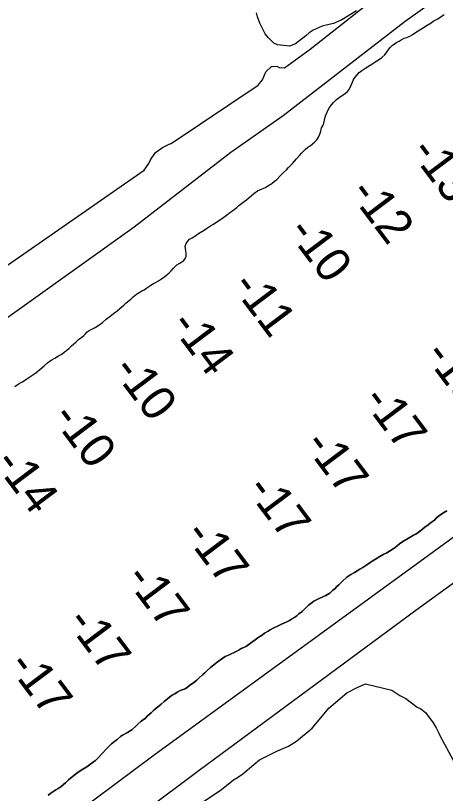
# Model space of a CAD drawing. Extents: x 3683613 to 3738215, y 469626 to 495384.
# Drawn here: x 3693984 to 3694543, y 491252 to 492263 of the extents above; entities that cross this region are included whole.
import ezdxf

# ---------------------------------------------------------------- set-up
doc = ezdxf.new("R2010")
doc.units = 0
for name, color, linetype in [('V-LEVE-TOET', 7, 'Continuous'), ('V-RIVR-JETY', 7, 'Continuous'), ('V-SITE-VEGE', 7, 'Continuous'), ('V-TOPO-SHOR', 7, 'Continuous'), ('V-TOPO-SPOT', 7, 'Continuous')]:
    doc.layers.add(name, color=color, linetype=linetype)

msp = doc.modelspace()

# ---------------------------------------------------------------- linework, layer by layer
at = {"layer": 'V-LEVE-TOET'}
for points in [[(3695280.6, 492831.8), (3695045.1, 492660.8), (3694810.9, 492483.2), (3694490.9, 492255), (3694332.2, 492132.7), (3694264.1, 492084.7), (3694138.5, 491987.9), (3693926.7, 491837), (3693737.7, 491697.5), (3693640.3, 491627.5), (3693587.1, 491587.3), (3693561.1, 491567.6), (3693375.6, 491432.8), (3693131.5, 491252.5)], [(3693943.4, 491917.9), (3694151.5, 492062.1), (3694157.4, 492070.6), (3694159.6, 492075.3), (3694166.3, 492084.7), (3694175.5, 492091.5), (3694184.1, 492095.6), (3694186.6, 492096.6), (3694299.6, 492172.4), (3694305.2, 492179.1), (3694309.5, 492189.6), (3694316.8, 492196.4), (3694323.9, 492197.1), (3694326.9, 492195.1), (3694333.8, 492194.9), (3694367.2, 492219.1), (3694555.4, 492367.6)], [(3692742.2, 490254.9), (3693119.2, 490531), (3693505.2, 490808.5), (3693831.6, 491054.9), (3694164.5, 491302.4), (3694594.4, 491615), (3694776.6, 491744.1), (3694908.8, 491836.2), (3695045.7, 491937.3), (3695073, 491960.6), (3695095.4, 491971.2), (3695099.9, 491970), (3695106.2, 491964.6), (3695111.3, 491953.8), (3695114, 491939.2), (3695107.6, 491925.6), (3695067.8, 491896.4), (3694823.2, 491720.7), (3694504.8, 491489.9), (3694223, 491282.1), (3693783.2, 490953.5), (3693425, 490687.1), (3693111.9, 490453.6), (3692756, 490200.1)]]:
    msp.add_lwpolyline(points, dxfattribs=at)
at = {"layer": 'V-RIVR-JETY'}
for points in [[(3694404.5, 491523.4), (3694406.8, 491525.6), (3694409, 491527.8), (3694414.7, 491533.1), (3694420.3, 491536.7), (3694424.7, 491539.5), (3694431.9, 491543.6), (3694435.9, 491546), (3694442.1, 491550.2), (3694445.3, 491552.2), (3694448, 491554), (3694452.1, 491556.8), (3694457.8, 491560.1), (3694462.9, 491563.1), (3694466.7, 491565.1), (3694470.5, 491567.2), (3694475.2, 491570), (3694477.9, 491572), (3694480.5, 491574), (3694483.5, 491576.4), (3694487.9, 491579.6), (3694493, 491582.6), (3694498.1, 491585.8), (3694501.5, 491587.8), (3694504.5, 491589.3), (3694507.6, 491591.5), (3694511.1, 491594.1), (3694516.4, 491598.2), (3694520.8, 491601.1), (3694525.1, 491604.6), (3694528.9, 491607.4), (3694531.5, 491610.2), (3694533.9, 491612.4), (3694539.6, 491616.6), (3694544.7, 491619.6)], [(3694026.9, 491250), (3694030.3, 491252.6), (3694032.9, 491254.4), (3694036.7, 491257.2), (3694039.9, 491259), (3694043.7, 491261.4), (3694049.2, 491266.2), (3694053.3, 491270), (3694060.1, 491275.7), (3694064.2, 491278.9), (3694068.4, 491281.7), (3694071.8, 491283.9), (3694077.1, 491287), (3694080.5, 491289.4), (3694085.6, 491293.4), (3694088.2, 491295.2), (3694092.5, 491299.5), (3694096.1, 491303.5), (3694103.4, 491311), (3694106, 491313.7), (3694109, 491316.7), (3694113.3, 491320.1), (3694115.8, 491322.1), (3694120.6, 491326.5), (3694123.3, 491328.1), (3694129.7, 491331.7), (3694135.4, 491335.1), (3694140.9, 491340.1), (3694143.1, 491342.3), (3694147.6, 491346.4), (3694153.3, 491350.3), (3694155.5, 491352.6), (3694160.6, 491357.2), (3694164.2, 491360.4), (3694166.8, 491362.6), (3694173.6, 491368.5), (3694177.5, 491371.7), (3694181.7, 491375.3), (3694184.3, 491377.3), (3694187.9, 491379.9), (3694191.3, 491381.9), (3694194.5, 491383.9), (3694198.5, 491385.9), (3694204.6, 491388.4), (3694207.8, 491390.6), (3694210.3, 491392.4), (3694216.1, 491396.4), (3694219.9, 491399.4), (3694222.3, 491401.6), (3694227.8, 491406.8), (3694230.2, 491409.1), (3694233.2, 491411.9), (3694237.7, 491415.9), (3694242.2, 491419.5), (3694246.6, 491422.9), (3694253.9, 491428.3), (3694257, 491430.1), (3694261.1, 491432.1), (3694272, 491437.4), (3694274.8, 491439), (3694277.7, 491440.5), (3694280.9, 491442.1), (3694284.5, 491443.9), (3694289.6, 491447.7), (3694295.6, 491451.9), (3694299.2, 491454.3), (3694301.7, 491456.3), (3694305.1, 491458.3), (3694308.1, 491460.5), (3694312.6, 491463.3), (3694315.1, 491464.8), (3694319.1, 491467), (3694324.8, 491469.8), (3694330.1, 491472.1), (3694336, 491474.8), (3694340.2, 491477), (3694343.2, 491478.8), (3694346, 491480.6), (3694349.8, 491483.2), (3694352.6, 491485.6), (3694356.8, 491488.6), (3694360.9, 491492.8), (3694365, 491496.9), (3694369.7, 491500.5), (3694372.2, 491502.1), (3694378.3, 491505), (3694384.7, 491508.2), (3694387.6, 491509.5), (3694392.7, 491512.7), (3694396.1, 491515.9), (3694399.3, 491518.3), (3694401.9, 491521), (3694404.5, 491523.4)]]:
    msp.add_lwpolyline(points, dxfattribs=at)
at = {"layer": 'V-SITE-VEGE'}
for points in [[(3694427.5, 492269), (3694408.3, 492257.1), (3694397.7, 492252.6), (3694386.4, 492249.7), (3694382.7, 492249.1), (3694371.3, 492243.8), (3694366, 492240.3), (3694361.5, 492236.4), (3694348.3, 492226), (3694340.6, 492223), (3694325, 492224.6), (3694320.2, 492226.8), (3694312.8, 492234.2), (3694308.9, 492239.2), (3694304, 492248.6), (3694301.7, 492252.7), (3694298.7, 492261.2), (3694297.7, 492266.4)], [(3694228.8, 491241.8), (3694250.1, 491256.1), (3694258.4, 491262.7), (3694267.8, 491270), (3694272.7, 491273.1), (3694279.7, 491277.7), (3694294.1, 491290.1), (3694301.5, 491295.9), (3694324, 491307.3), (3694339, 491313.7), (3694349.7, 491320.2), (3694369.9, 491337.3), (3694383.2, 491353), (3694391.5, 491363.2), (3694415, 491383), (3694428.5, 491390.2), (3694435.4, 491393.2), (3694439.1, 491394.7)], [(3694439.1, 491394.7), (3694473.4, 491386.5), (3694484, 491379.8), (3694491.5, 491375.5)], [(3694491.5, 491375.5), (3694506.5, 491364.6), (3694511.2, 491362.1), (3694517.1, 491357.5), (3694527.2, 491344.3), (3694531, 491337.4), (3694534.4, 491330.5), (3694536.3, 491326.8), (3694553.1, 491295.7)]]:
    msp.add_lwpolyline(points, dxfattribs=at)
at = {"layer": 'V-TOPO-SHOR'}
for points in [[(3694317.3, 492044.8), (3694320.9, 492047.6), (3694323.9, 492050), (3694329.2, 492055.5), (3694332.5, 492058.9), (3694336.3, 492062.5), (3694339.1, 492065.2), (3694341.7, 492068), (3694344.2, 492070.6), (3694346.8, 492073.7), (3694349.4, 492076.5), (3694353.7, 492081.6), (3694356.1, 492084.2), (3694360.8, 492088.7), (3694364.2, 492091.7), (3694367.2, 492093.7), (3694370.2, 492096.3), (3694373.2, 492098.7), (3694375.8, 492101.3), (3694378.1, 492104.8), (3694379.9, 492108.9), (3694381.3, 492112.4), (3694382.2, 492116.8), (3694383.8, 492119.6), (3694384.9, 492123.1), (3694385.7, 492126.7), (3694387.3, 492132.4), (3694389.3, 492137.2), (3694390.6, 492140.5), (3694392.4, 492143.5), (3694394.8, 492146.6), (3694397.6, 492150), (3694401.5, 492153.9), (3694404.9, 492156.5), (3694407.8, 492158.5), (3694411.4, 492160.7), (3694415.7, 492163.9), (3694418.1, 492166.5), (3694420.7, 492172.5), (3694422.1, 492176.2), (3694423.6, 492179.5), (3694425.8, 492182.7), (3694428.4, 492185.6), (3694431, 492188.6), (3694434.2, 492191.2), (3694436.8, 492193.2), (3694439.7, 492195), (3694447.3, 492199.6), (3694450.5, 492201.8), (3694453.7, 492204), (3694457.3, 492205.9), (3694460.5, 492208.3), (3694464.2, 492211.8), (3694466.5, 492214.8), (3694469.4, 492218.9), (3694471.1, 492221.3), (3694473.9, 492223.8), (3694476.9, 492226.2), (3694480, 492228), (3694482.8, 492229.5), (3694485.5, 492231.3), (3694489.6, 492233.3), (3694492.9, 492234.2), (3694496.9, 492235.8), (3694499.7, 492237.6), (3694504.3, 492240.6), (3694509.9, 492244.3), (3694514.5, 492247.1), (3694519.4, 492250.3), (3694524.5, 492253.5), (3694527.1, 492255.3), (3694533, 492258.7), (3694538.7, 492262.2), (3694541.5, 492264)], [(3694509.9, 492244.3), (3694514.5, 492247.1), (3694519.4, 492250.3), (3694524.5, 492253.5), (3694527.1, 492255.3), (3694533, 492258.7), (3694538.7, 492262.2), (3694541.5, 492264)], [(3694200.6, 491942.7), (3694202.9, 491944.7), (3694204.9, 491947.2), (3694206, 491950), (3694206.1, 491953.8), (3694205.8, 491957.3), (3694204.9, 491963.4), (3694206.1, 491966.5), (3694208.3, 491969.7), (3694210.6, 491972.2), (3694213.8, 491974.2), (3694217.2, 491976.1), (3694221, 491978.7), (3694224.2, 491981.1), (3694229.3, 491984.1), (3694232.7, 491986.1), (3694237.8, 491989.5), (3694241.6, 491991.7), (3694248.4, 491996.5), (3694252, 491998.6), (3694255.2, 492001), (3694258.6, 492003.6), (3694264.1, 492007.6), (3694266.7, 492009.4), (3694272, 492013.4), (3694274.4, 492015.9), (3694281.4, 492021.3), (3694284.6, 492023.5), (3694290.8, 492028.9), (3694294, 492031.7), (3694298.6, 492035.1), (3694305, 492037.7), (3694309.4, 492039.4), (3694312.4, 492041.4), (3694317.3, 492044.8), (3694320.9, 492047.6), (3694323.9, 492050), (3694329.2, 492055.5), (3694332.5, 492058.9), (3694336.3, 492062.5), (3694339.1, 492065.2), (3694341.7, 492068), (3694344.2, 492070.6), (3694346.8, 492073.7), (3694349.4, 492076.5), (3694353.7, 492081.6), (3694356.1, 492084.2), (3694360.8, 492088.7), (3694364.2, 492091.7), (3694367.2, 492093.7), (3694370.2, 492096.3), (3694373.2, 492098.7), (3694375.8, 492101.3), (3694378.1, 492104.8), (3694379.9, 492108.9), (3694381.3, 492112.4), (3694382.2, 492116.8), (3694383.8, 492119.6), (3694384.9, 492123.1), (3694385.7, 492126.7), (3694387.3, 492132.4), (3694389.3, 492137.2), (3694390.6, 492140.5), (3694392.4, 492143.5), (3694394.8, 492146.6), (3694397.6, 492150), (3694401.5, 492153.9), (3694404.9, 492156.5), (3694407.8, 492158.5), (3694411.4, 492160.7), (3694415.7, 492163.9), (3694418.1, 492166.5), (3694420.7, 492172.5), (3694422.1, 492176.2), (3694423.6, 492179.5), (3694425.8, 492182.7), (3694428.4, 492185.6), (3694431, 492188.6), (3694434.2, 492191.2), (3694436.8, 492193.2), (3694439.7, 492195), (3694447.3, 492199.6), (3694450.5, 492201.8), (3694453.7, 492204), (3694457.3, 492205.9), (3694460.5, 492208.3), (3694464.2, 492211.8), (3694466.5, 492214.8), (3694469.4, 492218.9), (3694471.1, 492221.3), (3694473.9, 492223.8), (3694476.9, 492226.2), (3694480, 492228), (3694482.8, 492229.5), (3694485.5, 492231.3), (3694489.6, 492233.3), (3694492.9, 492234.2), (3694496.9, 492235.8), (3694499.7, 492237.6), (3694504.3, 492240.6), (3694509.9, 492244.3)], [(3693983.5, 491780.9), (3693986.3, 491783.1), (3693989.2, 491784.7), (3693993.2, 491786.9), (3693997.7, 491789.9), (3694003, 491793.7), (3694009.2, 491797.9), (3694012.8, 491800.5), (3694015.8, 491802.9), (3694021.5, 491807.7), (3694025.8, 491811.7), (3694030.7, 491815.1), (3694035.4, 491817.9), (3694040.2, 491820.9), (3694044.3, 491823), (3694047.9, 491825.9), (3694050.4, 491827.9), (3694054.1, 491830.9), (3694057.1, 491833.7), (3694059.6, 491835.9), (3694062.8, 491838.5), (3694066.3, 491841.8), (3694070.5, 491845.2), (3694073.1, 491847), (3694075.4, 491849.4), (3694077.6, 491851.8), (3694080.1, 491853.8), (3694084.4, 491855.8), (3694087.7, 491857.6), (3694092.4, 491860.6), (3694097.5, 491864.2), (3694102, 491868.2), (3694106.7, 491872), (3694111.6, 491875.8), (3694116.5, 491879.2), (3694120.1, 491882.2), (3694125, 491886.7), (3694128.2, 491889.7), (3694134, 491894.5), (3694137.2, 491897.3), (3694141.5, 491900.7), (3694145.7, 491903.5), (3694148.5, 491905.1), (3694151.4, 491906.7), (3694155, 491908.9), (3694157.6, 491910.7), (3694160.1, 491912.5), (3694163.7, 491914.6), (3694166.9, 491916.4), (3694170.3, 491918.4), (3694174.1, 491921), (3694178.2, 491924), (3694181.1, 491925.8), (3694183.9, 491928.6), (3694186.5, 491931), (3694189.7, 491934.5), (3694193.8, 491938.9), (3694196.8, 491940.7), (3694200.6, 491942.7), (3694202.9, 491944.7), (3694204.9, 491947.2), (3694206, 491950), (3694206.1, 491953.8), (3694205.8, 491957.3), (3694204.9, 491963.4), (3694206.1, 491966.5), (3694208.3, 491969.7), (3694210.6, 491972.2), (3694213.8, 491974.2), (3694217.2, 491976.1), (3694221, 491978.7), (3694224.2, 491981.1), (3694229.3, 491984.1), (3694232.7, 491986.1), (3694237.8, 491989.5), (3694241.6, 491991.7), (3694248.4, 491996.5), (3694252, 491998.6), (3694255.2, 492001), (3694258.6, 492003.6), (3694264.1, 492007.6), (3694266.7, 492009.4), (3694272, 492013.4), (3694274.4, 492015.9), (3694281.4, 492021.3), (3694284.6, 492023.5), (3694290.8, 492028.9), (3694294, 492031.7), (3694298.6, 492035.1), (3694305, 492037.7), (3694309.4, 492039.4), (3694312.4, 492041.4), (3694317.3, 492044.8)], [(3693983.5, 491780.9), (3693986.3, 491783.1), (3693989.2, 491784.7), (3693993.2, 491786.9), (3693997.7, 491789.9), (3694003, 491793.7), (3694009.2, 491797.9), (3694012.8, 491800.5), (3694015.8, 491802.9), (3694021.5, 491807.7), (3694025.8, 491811.7), (3694030.7, 491815.1), (3694035.4, 491817.9), (3694040.2, 491820.9), (3694044.3, 491823), (3694047.9, 491825.9), (3694050.4, 491827.9), (3694054.1, 491830.9), (3694057.1, 491833.7), (3694059.6, 491835.9), (3694062.8, 491838.5), (3694066.3, 491841.8), (3694070.5, 491845.2), (3694073.1, 491847), (3694075.4, 491849.4), (3694077.6, 491851.8), (3694080.1, 491853.8), (3694084.4, 491855.8), (3694087.7, 491857.6), (3694092.4, 491860.6), (3694097.5, 491864.2), (3694102, 491868.2), (3694106.7, 491872), (3694111.6, 491875.8), (3694116.5, 491879.2), (3694120.1, 491882.2), (3694125, 491886.7), (3694128.2, 491889.7), (3694134, 491894.5), (3694137.2, 491897.3), (3694141.5, 491900.7), (3694145.7, 491903.5), (3694148.5, 491905.1), (3694151.4, 491906.7), (3694155, 491908.9), (3694157.6, 491910.7), (3694160.1, 491912.5), (3694163.7, 491914.6), (3694166.9, 491916.4), (3694170.3, 491918.4), (3694174.1, 491921), (3694178.2, 491924), (3694181.1, 491925.8), (3694183.9, 491928.6), (3694186.5, 491931), (3694189.7, 491934.5), (3694193.8, 491938.9), (3694196.8, 491940.7), (3694200.6, 491942.7)], [(3694544.7, 491619.6), (3694539.6, 491616.6), (3694533.9, 491612.4), (3694531.5, 491610.2), (3694528.9, 491607.4), (3694525.1, 491604.6), (3694520.8, 491601.1), (3694516.4, 491598.2), (3694511.1, 491594.1), (3694507.6, 491591.5), (3694504.5, 491589.3), (3694501.5, 491587.8), (3694498.1, 491585.8), (3694493, 491582.6), (3694487.9, 491579.6), (3694483.5, 491576.4), (3694480.5, 491574), (3694477.9, 491572), (3694475.2, 491570), (3694470.5, 491567.2), (3694466.7, 491565.1), (3694462.9, 491563.1), (3694457.8, 491560.1), (3694452.1, 491556.8), (3694448, 491554), (3694445.3, 491552.2), (3694442.1, 491550.2), (3694435.9, 491546), (3694431.9, 491543.6), (3694424.7, 491539.5), (3694420.3, 491536.7), (3694414.7, 491533.1), (3694409, 491527.8), (3694406.8, 491525.6), (3694404.5, 491523.4), (3694401.9, 491521), (3694399.3, 491518.3), (3694396.1, 491515.9), (3694392.7, 491512.7), (3694387.6, 491509.5), (3694384.7, 491508.2), (3694378.3, 491505), (3694372.2, 491502.1), (3694369.7, 491500.5), (3694365, 491496.9), (3694360.9, 491492.8), (3694356.8, 491488.6), (3694352.6, 491485.6), (3694349.8, 491483.2), (3694346, 491480.6), (3694343.2, 491478.8), (3694340.2, 491477), (3694336, 491474.8), (3694330.1, 491472.1), (3694324.8, 491469.8), (3694319.1, 491467), (3694315.1, 491464.8), (3694312.6, 491463.3), (3694308.1, 491460.5), (3694305.1, 491458.3), (3694301.7, 491456.3), (3694299.2, 491454.3), (3694295.6, 491451.9), (3694289.6, 491447.7), (3694284.5, 491443.9), (3694280.9, 491442.1), (3694277.7, 491440.5), (3694274.8, 491439), (3694272, 491437.4), (3694261.1, 491432.1), (3694257, 491430.1), (3694253.9, 491428.3), (3694246.6, 491422.9), (3694242.2, 491419.5), (3694237.7, 491415.9), (3694233.2, 491411.9), (3694230.2, 491409.1), (3694227.8, 491406.8), (3694222.3, 491401.6), (3694219.9, 491399.4), (3694216.1, 491396.4), (3694210.3, 491392.4), (3694207.8, 491390.6), (3694204.6, 491388.4), (3694198.5, 491385.9), (3694194.5, 491383.9), (3694191.3, 491381.9), (3694187.9, 491379.9), (3694184.3, 491377.3), (3694181.7, 491375.3), (3694177.5, 491371.7), (3694173.6, 491368.5), (3694166.8, 491362.6), (3694164.2, 491360.4), (3694160.6, 491357.2), (3694155.5, 491352.6), (3694153.3, 491350.3), (3694147.6, 491346.4), (3694143.1, 491342.3), (3694140.9, 491340.1), (3694135.4, 491335.1)], [(3694404.5, 491523.4), (3694406.8, 491525.6), (3694409, 491527.8), (3694414.7, 491533.1), (3694420.3, 491536.7), (3694424.7, 491539.5), (3694431.9, 491543.6), (3694435.9, 491546), (3694442.1, 491550.2), (3694445.3, 491552.2), (3694448, 491554), (3694452.1, 491556.8), (3694457.8, 491560.1), (3694462.9, 491563.1), (3694466.7, 491565.1), (3694470.5, 491567.2), (3694475.2, 491570), (3694477.9, 491572), (3694480.5, 491574), (3694483.5, 491576.4), (3694487.9, 491579.6), (3694493, 491582.6), (3694498.1, 491585.8), (3694501.5, 491587.8), (3694504.5, 491589.3), (3694507.6, 491591.5), (3694511.1, 491594.1), (3694516.4, 491598.2), (3694520.8, 491601.1), (3694525.1, 491604.6), (3694528.9, 491607.4), (3694531.5, 491610.2), (3694533.9, 491612.4), (3694539.6, 491616.6), (3694544.7, 491619.6)], [(3694026.9, 491250), (3694030.3, 491252.6), (3694032.9, 491254.4), (3694036.7, 491257.2), (3694039.9, 491259), (3694043.7, 491261.4), (3694049.2, 491266.2), (3694053.3, 491270), (3694060.1, 491275.7), (3694064.2, 491278.9), (3694068.4, 491281.7), (3694071.8, 491283.9), (3694077.1, 491287), (3694080.5, 491289.4), (3694085.6, 491293.4), (3694088.2, 491295.2), (3694092.5, 491299.5), (3694096.1, 491303.5), (3694103.4, 491311), (3694106, 491313.7), (3694109, 491316.7), (3694113.3, 491320.1), (3694115.8, 491322.1), (3694120.6, 491326.5), (3694123.3, 491328.1), (3694129.7, 491331.7), (3694135.4, 491335.1), (3694140.9, 491340.1), (3694143.1, 491342.3), (3694147.6, 491346.4), (3694153.3, 491350.3), (3694155.5, 491352.6), (3694160.6, 491357.2), (3694164.2, 491360.4), (3694166.8, 491362.6), (3694173.6, 491368.5), (3694177.5, 491371.7), (3694181.7, 491375.3), (3694184.3, 491377.3), (3694187.9, 491379.9), (3694191.3, 491381.9), (3694194.5, 491383.9), (3694198.5, 491385.9), (3694204.6, 491388.4), (3694207.8, 491390.6), (3694210.3, 491392.4), (3694216.1, 491396.4), (3694219.9, 491399.4), (3694222.3, 491401.6), (3694227.8, 491406.8), (3694230.2, 491409.1), (3694233.2, 491411.9), (3694237.7, 491415.9), (3694242.2, 491419.5), (3694246.6, 491422.9), (3694253.9, 491428.3), (3694257, 491430.1), (3694261.1, 491432.1), (3694272, 491437.4), (3694274.8, 491439), (3694277.7, 491440.5), (3694280.9, 491442.1), (3694284.5, 491443.9), (3694289.6, 491447.7), (3694295.6, 491451.9), (3694299.2, 491454.3), (3694301.7, 491456.3), (3694305.1, 491458.3), (3694308.1, 491460.5), (3694312.6, 491463.3), (3694315.1, 491464.8), (3694319.1, 491467), (3694324.8, 491469.8), (3694330.1, 491472.1), (3694336, 491474.8), (3694340.2, 491477), (3694343.2, 491478.8), (3694346, 491480.6), (3694349.8, 491483.2), (3694352.6, 491485.6), (3694356.8, 491488.6), (3694360.9, 491492.8), (3694365, 491496.9), (3694369.7, 491500.5), (3694372.2, 491502.1), (3694378.3, 491505), (3694384.7, 491508.2), (3694387.6, 491509.5), (3694392.7, 491512.7), (3694396.1, 491515.9), (3694399.3, 491518.3), (3694401.9, 491521), (3694404.5, 491523.4)], [(3694135.4, 491335.1), (3694129.7, 491331.7), (3694123.3, 491328.1), (3694120.6, 491326.5), (3694115.8, 491322.1), (3694113.3, 491320.1), (3694109, 491316.7), (3694106, 491313.7), (3694103.4, 491311), (3694096.1, 491303.5), (3694092.5, 491299.5), (3694088.2, 491295.2), (3694085.6, 491293.4), (3694080.5, 491289.4), (3694077.1, 491287), (3694071.8, 491283.9), (3694068.4, 491281.7), (3694064.2, 491278.9), (3694060.1, 491275.7), (3694053.3, 491270), (3694049.2, 491266.2), (3694043.7, 491261.4), (3694039.9, 491259), (3694036.7, 491257.2), (3694032.9, 491254.4), (3694030.3, 491252.6), (3694026.9, 491250)]]:
    msp.add_lwpolyline(points, dxfattribs=at)

# ---------------------------------------------------------------- texts
at = {"layer": 'V-TOPO-SPOT'}
for s, p in [('-13', (3694496.1, 492085.7)), ('-12', (3694417, 492032.2)), ('-10', (3694336.6, 491981.8)), ('-11', (3694264, 491911.4)), ('-14', (3694184, 491860.9)), ('-18', (3694514.3, 491821.7)), ('-10', (3694109.1, 491802.2)), ('-17', (3694433.9, 491763)), ('-10', (3694030.2, 491740.7)), ('-17', (3694357.9, 491705.4)), ('-14', (3693955.2, 491681.4)), ('-17', (3694282.9, 491647.1)), ('-17', (3694202.3, 491588.6)), ('-17', (3694125.3, 491531.8)), ('-17', (3694049.2, 491475)), ('-17', (3693973.1, 491418.4))]:
    msp.add_text(s, height=45, rotation=306.9347, dxfattribs=at).set_placement(p)

doc.saveas('drawing.dxf')
